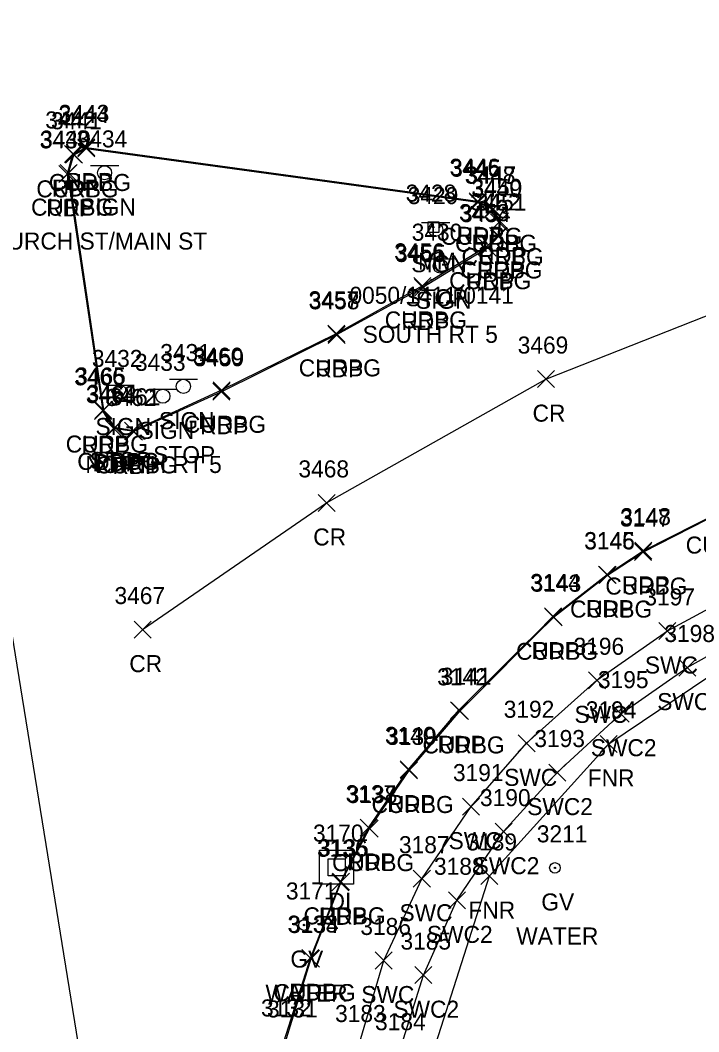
# Model space of a CAD drawing. Extents: x 1690689 to 1696275, y 438760 to 444007.
# Drawn here: x 1691116.4 to 1691196.2, y 442311.5 to 442430.3 of the extents above; entities that cross this region are included whole.
import ezdxf

# ---------------------------------------------------------------- set-up
doc = ezdxf.new("R2010")
doc.units = 0
for name, color, linetype in [('D_A', 7, 'Continuous'), ('D_I', 7, 'Continuous'), ('DS', 7, 'Continuous'), ('L_A', 7, 'Continuous'), ('L_I', 7, 'Continuous'), ('L_TIC', 7, 'Continuous'), ('LFNC', 7, 'Continuous'), ('P_A', 7, 'Continuous'), ('P_I', 7, 'Continuous'), ('P_TIC', 7, 'Continuous'), ('PET', 7, 'Continuous'), ('PRC', 7, 'Continuous'), ('R_A', 7, 'Continuous'), ('R_I', 7, 'Continuous'), ('R_TIC', 7, 'Continuous'), ('RC', 7, 'Continuous'), ('RSW', 7, 'Continuous'), ('S_A', 7, 'Continuous'), ('S_C', 7, 'Continuous'), ('S_I', 7, 'Continuous'), ('SRM', 7, 'Continuous'), ('SSGN', 7, 'Continuous'), ('U_A', 7, 'Continuous'), ('U_C', 7, 'Continuous'), ('U_I', 7, 'Continuous'), ('UWV', 7, 'Continuous')]:
    doc.layers.add(name, color=color, linetype=linetype)

msp = doc.modelspace()

# ---------------------------------------------------------------- linework, layer by layer
at = {"layer": 'DS'}
for p, q in [((1691151.61, 442332.83), (1691155.61, 442332.83)), ((1691151.61, 442328.83), (1691151.61, 442332.83)), ((1691155.61, 442332.83), (1691155.61, 442328.83)), ((1691152.61, 442329.83), (1691152.61, 442331.83)), ((1691152.61, 442331.83), (1691154.61, 442331.83)), ((1691154.61, 442331.83), (1691154.61, 442329.83)), ((1691154.61, 442329.83), (1691152.61, 442329.83)), ((1691153.62, 442330.84), (1691153.62, 442330.84)), ((1691153.62, 442330.84), (1691153.62, 442330.84)), ((1691155.61, 442328.83), (1691151.61, 442328.83))]:
    msp.add_line(p, q, dxfattribs=at)
at = {"layer": 'L_TIC'}
for points in [[(1691184.61, 442344.32), (1691186.61, 442346.32)], [(1691186.61, 442344.32), (1691184.61, 442346.32)], [(1691170.58, 442328.8), (1691172.58, 442330.8)], [(1691172.58, 442328.8), (1691170.58, 442330.8)]]:
    msp.add_lwpolyline(points, dxfattribs=at)
at = {"layer": 'LFNC'}
msp.add_lwpolyline([(1691164.13, 442250.32), (1691161.43, 442265.64), (1691160.13, 442277.98), (1691159.64, 442292.43), (1691171.58, 442329.8), (1691185.61, 442345.32), (1691203.26, 442357.19), (1691223.43, 442363.14), (1691244.19, 442366.11)], dxfattribs=at)
at = {"layer": 'P_TIC'}
for points in [[(1691121.62, 442413.63), (1691123.62, 442415.63)], [(1691123.62, 442413.63), (1691121.62, 442415.63)], [(1691123.2, 442414.4), (1691125.2, 442416.4)], [(1691125.2, 442414.4), (1691123.2, 442416.4)], [(1691120.97, 442411.29), (1691122.97, 442413.29)], [(1691122.97, 442411.29), (1691120.97, 442413.29)], [(1691120.97, 442411.29), (1691122.97, 442413.29)], [(1691122.97, 442411.29), (1691120.97, 442413.29)], [(1691169.21, 442408.07), (1691171.21, 442410.07)], [(1691171.21, 442408.07), (1691169.21, 442410.07)], [(1691171.04, 442407.16), (1691173.04, 442409.16)], [(1691173.04, 442407.16), (1691171.04, 442409.16)], [(1691171.84, 442405.7), (1691173.84, 442407.7)], [(1691173.84, 442405.7), (1691171.84, 442407.7)], [(1691171.68, 442403.98), (1691173.68, 442405.98)], [(1691173.68, 442403.98), (1691171.68, 442405.98)], [(1691170.39, 442402.62), (1691172.39, 442404.62)], [(1691172.39, 442402.62), (1691170.39, 442404.62)], [(1691162.76, 442397.94), (1691164.76, 442399.94)], [(1691164.76, 442397.94), (1691162.76, 442399.94)], [(1691152.62, 442392.38), (1691154.62, 442394.38)], [(1691154.62, 442392.38), (1691152.62, 442394.38)], [(1691177.23, 442387.18), (1691179.23, 442389.18)], [(1691179.23, 442387.18), (1691177.23, 442389.18)], [(1691139.07, 442385.69), (1691141.07, 442387.69)], [(1691141.07, 442385.69), (1691139.07, 442387.69)], [(1691125.13, 442383.45), (1691127.13, 442385.45)], [(1691127.13, 442383.45), (1691125.13, 442385.45)], [(1691125.13, 442383.45), (1691127.13, 442385.45)], [(1691127.13, 442383.45), (1691125.13, 442385.45)], [(1691126.43, 442381.36), (1691128.43, 442383.36)], [(1691128.43, 442381.36), (1691126.43, 442383.36)], [(1691128.78, 442381.02), (1691130.78, 442383.02)], [(1691130.78, 442381.02), (1691128.78, 442383.02)], [(1691151.44, 442372.63), (1691153.44, 442374.63)], [(1691153.44, 442372.63), (1691151.44, 442374.63)], [(1691188.67, 442367.02), (1691190.67, 442369.02)], [(1691190.67, 442367.02), (1691188.67, 442369.02)], [(1691184.42, 442364.21), (1691186.42, 442366.21)], [(1691186.42, 442364.21), (1691184.42, 442366.21)], [(1691178.07, 442359.29), (1691180.07, 442361.29)], [(1691180.07, 442359.29), (1691178.07, 442361.29)], [(1691129.81, 442357.75), (1691131.81, 442359.75)], [(1691131.81, 442357.75), (1691129.81, 442359.75)], [(1691167, 442348.27), (1691169, 442350.27)], [(1691169, 442348.27), (1691167, 442350.27)], [(1691161.08, 442341.32), (1691163.08, 442343.32)], [(1691163.08, 442341.32), (1691161.08, 442343.32)], [(1691156.38, 442334.47), (1691158.38, 442336.47)], [(1691158.38, 442334.47), (1691156.38, 442336.47)], [(1691153.06, 442328.06), (1691155.06, 442330.06)], [(1691155.06, 442328.06), (1691153.06, 442330.06)], [(1691149.53, 442319.15), (1691151.53, 442321.15)], [(1691151.53, 442319.15), (1691149.53, 442321.15)]]:
    msp.add_lwpolyline(points, dxfattribs=at)
at = {"layer": 'PET'}
for points in [[(1691121.97, 442412.29), (1691122.62, 442414.63), (1691124.2, 442415.4), (1691170.21, 442409.07), (1691172.04, 442408.16), (1691172.84, 442406.7), (1691172.68, 442404.98), (1691171.39, 442403.62), (1691163.76, 442398.94), (1691153.62, 442393.38), (1691140.07, 442386.69), (1691129.78, 442382.02), (1691127.43, 442382.36), (1691126.13, 442384.45)], [(1691121.97, 442412.29), (1691126.13, 442384.45)], [(1691147.42, 442310.3), (1691150.53, 442320.15), (1691154.06, 442329.06), (1691157.38, 442335.47), (1691162.08, 442342.32), (1691168, 442349.27), (1691179.07, 442360.29), (1691185.42, 442365.21), (1691189.67, 442368.02), (1691199.04, 442372.75), (1691205.16, 442375.21), (1691212.79, 442377.84), (1691220.73, 442380.07), (1691237.55, 442384.25), (1691258.48, 442389.38), (1691261.52, 442389.58), (1691265.35, 442388.29), (1691276.53, 442377.73), (1691276.93, 442377.8)]]:
    msp.add_lwpolyline(points, dxfattribs=at)
at = {"layer": 'PRC'}
for points in [[(1691277.81, 441080.96), (1691253.5, 441214.94), (1691246.19, 441267.52), (1691239.79, 441327.83), (1691235.79, 441375.29), (1691233.27, 441422.2), (1691229.73, 441505.18), (1691226.6, 441557.92), (1691222.02, 441618.83), (1691218.57, 441657.04), (1691144.02, 442182.42), (1691112.43, 442376.83), (1691097.75, 442454.48), (1691089.73, 442499.13), (1691078.44, 442565.84)], [(1691130.81, 442358.75), (1691152.44, 442373.63), (1691178.23, 442388.18), (1691209.8, 442400.63), (1691248.04, 442408.48), (1691275.24, 442412.28), (1691309.15, 442415.93), (1691347.17, 442419.98), (1691395.19, 442425.91), (1691433.65, 442431.72), (1691478.76, 442438.88), (1691513.2, 442445.49), (1691566.06, 442456.6), (1691813.76, 442512.5), (1691980.06, 442550.02), (1692039.61, 442563.23)]]:
    msp.add_lwpolyline(points, dxfattribs=at)
at = {"layer": 'R_TIC'}
for points in [[(1691121.73, 442413.53), (1691123.73, 442415.53)], [(1691123.73, 442413.53), (1691121.73, 442415.53)], [(1691123.18, 442414.28), (1691125.18, 442416.28)], [(1691125.18, 442414.28), (1691123.18, 442416.28)], [(1691121.1, 442411.38), (1691123.1, 442413.38)], [(1691123.1, 442411.38), (1691121.1, 442413.38)], [(1691121.1, 442411.38), (1691123.1, 442413.38)], [(1691123.1, 442411.38), (1691121.1, 442413.38)], [(1691169.24, 442407.96), (1691171.24, 442409.96)], [(1691171.24, 442407.96), (1691169.24, 442409.96)], [(1691170.95, 442407.14), (1691172.95, 442409.14)], [(1691172.95, 442407.14), (1691170.95, 442409.14)], [(1691171.72, 442405.58), (1691173.72, 442407.58)], [(1691173.72, 442405.58), (1691171.72, 442407.58)], [(1691171.58, 442404), (1691173.58, 442406)], [(1691173.58, 442404), (1691171.58, 442406)], [(1691170.27, 442402.74), (1691172.27, 442404.74)], [(1691172.27, 442402.74), (1691170.27, 442404.74)], [(1691162.7, 442398.13), (1691164.7, 442400.13)], [(1691164.7, 442398.13), (1691162.7, 442400.13)], [(1691152.58, 442392.5), (1691154.58, 442394.5)], [(1691154.58, 442392.5), (1691152.58, 442394.5)], [(1691139.09, 442385.87), (1691141.09, 442387.87)], [(1691141.09, 442385.87), (1691139.09, 442387.87)], [(1691125.19, 442383.55), (1691127.19, 442385.55)], [(1691127.19, 442383.55), (1691125.19, 442385.55)], [(1691125.19, 442383.55), (1691127.19, 442385.55)], [(1691127.19, 442383.55), (1691125.19, 442385.55)], [(1691126.54, 442381.51), (1691128.54, 442383.51)], [(1691128.54, 442381.51), (1691126.54, 442383.51)], [(1691128.68, 442381.1), (1691130.68, 442383.1)], [(1691130.68, 442381.1), (1691128.68, 442383.1)], [(1691188.64, 442366.86), (1691190.64, 442368.86)], [(1691190.64, 442366.86), (1691188.64, 442368.86)], [(1691184.49, 442364.16), (1691186.49, 442366.16)], [(1691186.49, 442364.16), (1691184.49, 442366.16)], [(1691178.14, 442359.2), (1691180.14, 442361.2)], [(1691180.14, 442359.2), (1691178.14, 442361.2)], [(1691191.51, 442357.59), (1691193.51, 442359.59)], [(1691193.51, 442357.59), (1691191.51, 442359.59)], [(1691193.85, 442353.29), (1691195.85, 442355.29)], [(1691195.85, 442353.29), (1691193.85, 442355.29)], [(1691183.23, 442351.79), (1691185.23, 442353.79)], [(1691185.23, 442351.79), (1691183.23, 442353.79)], [(1691167.14, 442348.2), (1691169.14, 442350.2)], [(1691169.14, 442348.2), (1691167.14, 442350.2)], [(1691186.04, 442347.87), (1691188.04, 442349.87)], [(1691188.04, 442347.87), (1691186.04, 442349.87)], [(1691174.96, 442344.39), (1691176.96, 442346.39)], [(1691176.96, 442344.39), (1691174.96, 442346.39)], [(1691161.15, 442341.2), (1691163.15, 442343.2)], [(1691163.15, 442341.2), (1691161.15, 442343.2)], [(1691178.56, 442340.95), (1691180.56, 442342.95)], [(1691180.56, 442340.95), (1691178.56, 442342.95)], [(1691168.43, 442336.95), (1691170.43, 442338.95)], [(1691170.43, 442336.95), (1691168.43, 442338.95)], [(1691156.5, 442334.37), (1691158.5, 442336.37)], [(1691158.5, 442334.37), (1691156.5, 442336.37)], [(1691172.26, 442334.01), (1691174.26, 442336.01)], [(1691174.26, 442334.01), (1691172.26, 442336.01)], [(1691153.14, 442328.12), (1691155.14, 442330.12)], [(1691155.14, 442328.12), (1691153.14, 442330.12)], [(1691162.64, 442328.48), (1691164.64, 442330.48)], [(1691164.64, 442328.48), (1691162.64, 442330.48)], [(1691166.77, 442325.94), (1691168.77, 442327.94)], [(1691168.77, 442325.94), (1691166.77, 442327.94)], [(1691149.62, 442319.1), (1691151.62, 442321.1)], [(1691151.62, 442319.1), (1691149.62, 442321.1)], [(1691158.16, 442318.87), (1691160.16, 442320.87)], [(1691160.16, 442318.87), (1691158.16, 442320.87)], [(1691162.82, 442317.15), (1691164.82, 442319.15)], [(1691164.82, 442317.15), (1691162.82, 442319.15)]]:
    msp.add_lwpolyline(points, dxfattribs=at)
at = {"layer": 'RC'}
for points in [[(1691122.1, 442412.38), (1691122.73, 442414.53), (1691124.18, 442415.28), (1691170.24, 442408.96), (1691171.95, 442408.14), (1691172.72, 442406.58), (1691172.58, 442405), (1691171.27, 442403.74), (1691163.7, 442399.13), (1691153.58, 442393.5), (1691140.09, 442386.87), (1691129.68, 442382.1), (1691127.54, 442382.51), (1691126.19, 442384.55)], [(1691122.1, 442412.38), (1691126.19, 442384.55)], [(1691147.57, 442310.18), (1691150.62, 442320.1), (1691154.14, 442329.12), (1691157.5, 442335.37), (1691162.15, 442342.2), (1691168.14, 442349.2), (1691179.14, 442360.2), (1691185.49, 442365.16), (1691189.64, 442367.86), (1691199.09, 442372.68), (1691205.19, 442375.1), (1691212.81, 442377.67), (1691220.87, 442380.02), (1691237.57, 442384.16), (1691258.28, 442388.95)]]:
    msp.add_lwpolyline(points, dxfattribs=at)
at = {"layer": 'RSW'}
for points in [[(1691173.65, 442147.45), (1691164.24, 442181.45), (1691159.6, 442182.06), (1691158.97, 442186.8), (1691163.01, 442188.55), (1691166.55, 442192.36), (1691154.22, 442268.79), (1691153.3, 442278.85), (1691153.14, 442289.14), (1691154.2, 442299.81), (1691156.14, 442309.64), (1691159.16, 442319.87), (1691163.64, 442329.48), (1691169.43, 442337.95), (1691175.96, 442345.39), (1691184.23, 442352.79), (1691192.51, 442358.59), (1691201.39, 442363.4), (1691210.8, 442367.4), (1691220.98, 442369.51), (1691275.77, 442377.07), (1691323.58, 442378.78), (1691431.09, 442393.37)], [(1691168.85, 442209.69), (1691163.66, 442242.11), (1691162.54, 442249.93), (1691158.99, 442269.5), (1691158.08, 442288.93), (1691158.91, 442298.99), (1691160.84, 442308.68), (1691163.82, 442318.15), (1691167.77, 442326.94), (1691173.26, 442335.01), (1691179.56, 442341.95), (1691187.04, 442348.87), (1691194.85, 442354.29), (1691203.45, 442359.11), (1691212.34, 442362.71), (1691221.77, 442364.59), (1691276.88, 442372.18)]]:
    msp.add_lwpolyline(points, dxfattribs=at)
at = {"layer": 'SRM'}
msp.add_lwpolyline([(1691164.38, 442406.65), (1691165.63, 442406.65), (1691165.63, 442405.4), (1691164.38, 442405.4)], close=True, dxfattribs=at)
msp.add_circle((1691165, 442406.03), 0.0833, dxfattribs=at)
at = {"layer": 'SSGN'}
for p, q in [((1691124.68, 442413.26), (1691128.01, 442413.26)), ((1691126.33, 442412.42), (1691126.33, 442412.42)), ((1691163.62, 442406.59), (1691166.95, 442406.59)), ((1691165.26, 442405.76), (1691165.26, 442405.76)), ((1691164.17, 442402.29), (1691167.5, 442402.29)), ((1691165.81, 442401.46), (1691165.81, 442401.46)), ((1691133.95, 442388.16), (1691137.28, 442388.16)), ((1691126.47, 442387.46), (1691129.8, 442387.46)), ((1691131.55, 442387), (1691134.88, 442387)), ((1691135.6, 442387.32), (1691135.6, 442387.32)), ((1691128.12, 442386.63), (1691128.12, 442386.63)), ((1691133.19, 442386.17), (1691133.19, 442386.17))]:
    msp.add_line(p, q, dxfattribs=at)
for centre in [(1691126.33, 442412.42), (1691165.26, 442405.76), (1691165.81, 442401.46), (1691135.6, 442387.32), (1691128.12, 442386.63), (1691133.19, 442386.17)]:
    msp.add_circle(centre, 0.833, dxfattribs=at)
at = {"layer": 'UWV'}
for centre, radius in [((1691179.29, 442330.75), 0.625), ((1691179.29, 442330.75), 0.0833), ((1691149.79, 442324.04), 0.625), ((1691149.79, 442324.04), 0.0833)]:
    msp.add_circle(centre, radius, dxfattribs=at)

# ---------------------------------------------------------------- texts
at = {"layer": 'D_A'}
msp.add_text('DI', height=2, dxfattribs=at).set_placement((1691152.67, 442325.84))
at = {"layer": 'D_I'}
msp.add_text('3170', height=2, dxfattribs=at).set_placement((1691150.84, 442333.84))
at = {"layer": 'L_A'}
for p in [(1691183.15, 442340.32), (1691169.12, 442324.8)]:
    msp.add_text('FNR', height=2, dxfattribs=at).set_placement(p)
at = {"layer": 'L_I'}
for s, p in [('3194', (1691182.92, 442348.32)), ('3189', (1691168.88, 442332.8))]:
    msp.add_text(s, height=2, dxfattribs=at).set_placement(p)
at = {"layer": 'P_A'}
for s, p in [('RDP', (1691121.69, 442410.4)), ('RDP', (1691120.11, 442409.63)), ('RDP', (1691119.45, 442407.29)), ('RDP', (1691119.45, 442407.29)), ('RDP', (1691167.7, 442404.07)), ('RDP', (1691169.52, 442403.16)), ('RDP', (1691170.33, 442401.7)), ('RDP', (1691170.16, 442399.98)), ('RDP', (1691168.88, 442398.62)), ('RDP', (1691161.24, 442393.94)), ('RDP', (1691151.11, 442388.38)), ('CR', (1691176.66, 442383.18)), ('RDP', (1691137.56, 442381.69)), ('RDP', (1691123.61, 442379.45)), ('RDP', (1691123.61, 442379.45)), ('RDP', (1691124.92, 442377.36)), ('RDP', (1691127.26, 442377.02)), ('CR', (1691150.87, 442368.63)), ('RDP', (1691187.16, 442363.02)), ('RDP', (1691182.91, 442360.21)), ('RDP', (1691176.55, 442355.29)), ('CR', (1691129.24, 442353.75)), ('RDP', (1691165.48, 442344.27)), ('RDP', (1691159.57, 442337.32)), ('RDP', (1691154.87, 442330.47)), ('RDP', (1691151.54, 442324.06)), ('RDP', (1691148.02, 442315.15))]:
    msp.add_text(s, height=2, dxfattribs=at).set_placement(p)
at = {"layer": 'P_I'}
for s, p in [('3443', (1691120.94, 442418.4)), ('3442', (1691119.36, 442417.63)), ('3439', (1691118.7, 442415.29)), ('3439', (1691118.7, 442415.29)), ('3446', (1691166.9, 442412.07)), ('3447', (1691168.78, 442411.16)), ('3450', (1691169.49, 442409.7)), ('3451', (1691169.98, 442407.98)), ('3454', (1691168.13, 442406.62)), ('3455', (1691160.5, 442401.94)), ('3458', (1691150.36, 442396.38)), ('3469', (1691174.91, 442391.18)), ('3459', (1691136.8, 442389.69)), ('3466', (1691122.76, 442387.45)), ('3466', (1691122.76, 442387.45)), ('3463', (1691124.13, 442385.36)), ('3462', (1691126.47, 442385.02)), ('3468', (1691149.13, 442376.63)), ('3148', (1691186.98, 442371.02)), ('3145', (1691182.73, 442368.21)), ('3144', (1691176.37, 442363.29)), ('3467', (1691127.5, 442361.75)), ('3141', (1691165.87, 442352.27)), ('3140', (1691159.3, 442345.32)), ('3137', (1691154.68, 442338.47)), ('3136', (1691151.31, 442332.06)), ('3133', (1691147.84, 442323.15)), ('3132', (1691144.73, 442313.3))]:
    msp.add_text(s, height=2, dxfattribs=at).set_placement(p)
at = {"layer": 'R_A'}
for s, p in [('CURBG', (1691119.77, 442410.28)), ('CURBG', (1691118.31, 442409.53)), ('CURBG', (1691117.69, 442407.38)), ('CURBG', (1691117.69, 442407.38)), ('CURBG', (1691165.82, 442403.96)), ('CURBG', (1691167.54, 442403.14)), ('CURBG', (1691168.31, 442401.58)), ('CURBG', (1691168.17, 442400)), ('CURBG', (1691166.85, 442398.74)), ('CURBG', (1691159.28, 442394.13)), ('CURBG', (1691149.17, 442388.5)), ('CURBG', (1691135.67, 442381.87)), ('CURBG', (1691121.77, 442379.55)), ('CURBG', (1691121.77, 442379.55)), ('CURBG', (1691123.12, 442377.51)), ('CURBG', (1691125.26, 442377.1)), ('CURBG', (1691194.67, 442367.68)), ('CURBG', (1691185.22, 442362.86)), ('CURBG', (1691181.07, 442360.16)), ('CURBG', (1691174.72, 442355.2)), ('SWC', (1691189.87, 442353.59)), ('SWC2', (1691191.32, 442349.29)), ('SWC', (1691181.59, 442347.79)), ('CURBG', (1691163.72, 442344.2)), ('SWC2', (1691183.51, 442343.87)), ('SWC', (1691173.32, 442340.39)), ('CURBG', (1691157.73, 442337.2)), ('SWC2', (1691176.03, 442336.95)), ('SWC', (1691166.79, 442332.95)), ('CURBG', (1691153.08, 442330.37)), ('SWC2', (1691169.73, 442330.01)), ('SWC', (1691161.01, 442324.48)), ('CURBG', (1691149.72, 442324.12)), ('SWC2', (1691164.24, 442321.94)), ('CURBG', (1691146.2, 442315.1)), ('SWC', (1691156.52, 442314.87)), ('SWC2', (1691160.3, 442313.15))]:
    msp.add_text(s, height=2, dxfattribs=at).set_placement(p)
at = {"layer": 'R_I'}
for s, p in [('3444', (1691120.92, 442418.28)), ('3441', (1691120.04, 442417.53)), ('3440', (1691118.76, 442415.38)), ('3440', (1691118.76, 442415.38)), ('3445', (1691166.98, 442411.96)), ('3448', (1691168.69, 442411.14)), ('3449', (1691169.46, 442409.58)), ('3452', (1691169.32, 442408)), ('3453', (1691168.01, 442406.74)), ('3456', (1691160.39, 442402.13)), ('3457', (1691150.32, 442396.5)), ('3460', (1691136.7, 442389.87)), ('3465', (1691122.88, 442387.55)), ('3465', (1691122.88, 442387.55)), ('3464', (1691124.23, 442385.51)), ('3461', (1691126.94, 442385.1)), ('3147', (1691186.94, 442370.86)), ('3146', (1691182.74, 442368.16)), ('3143', (1691176.44, 442363.2)), ('3197', (1691189.81, 442361.59)), ('3198', (1691192.16, 442357.29)), ('3196', (1691181.48, 442355.79)), ('3142', (1691165.44, 442352.2)), ('3195', (1691184.35, 442351.87)), ('3192', (1691173.27, 442348.39)), ('3139', (1691159.45, 442345.2)), ('3193', (1691176.87, 442344.95)), ('3191', (1691167.3, 442340.95)), ('3138', (1691154.81, 442338.37)), ('3190', (1691170.48, 442338.01)), ('3135', (1691151.45, 442332.12)), ('3187', (1691160.95, 442332.48)), ('3188', (1691165.07, 442329.94)), ('3134', (1691147.93, 442323.1)), ('3186', (1691156.41, 442322.87)), ('3185', (1691161.13, 442321.15)), ('3131', (1691145.44, 442313.18)), ('3183', (1691153.44, 442312.64)), ('3184', (1691158.14, 442311.68))]:
    msp.add_text(s, height=2, dxfattribs=at).set_placement(p)
at = {"layer": 'S_A'}
for s, p in [('SIGN', (1691123.46, 442407.4)), ('SIGN', (1691162.4, 442400.74)), ('MM', (1691163.19, 442401.03)), ('SIGN', (1691162.95, 442396.44)), ('SIGN', (1691125.26, 442381.61)), ('SIGN', (1691132.73, 442382.3)), ('SIGN', (1691130.33, 442381.15))]:
    msp.add_text(s, height=2, dxfattribs=at).set_placement(p)
at = {"layer": 'S_C'}
for s, p in [('CHURCH ST/MAIN ST', (1691111.06, 442403.4)), ('0050/1411/0141', (1691155.13, 442397.03)), ('STOP', (1691161.73, 442396.74)), ('SOUTH RT 5', (1691156.68, 442392.44)), ('STOP', (1691132.06, 442378.3)), ('NORTH RT 5', (1691124.07, 442377.15)), ('STOP', (1691124.58, 442377.61))]:
    msp.add_text(s, height=2, dxfattribs=at).set_placement(p)
at = {"layer": 'S_I'}
for s, p in [('3434', (1691123.05, 442415.4)), ('3428', (1691161.74, 442409.03)), ('3429', (1691161.98, 442408.74)), ('3430', (1691162.45, 442404.44)), ('3432', (1691124.84, 442389.61)), ('3431', (1691132.88, 442390.3)), ('3433', (1691129.91, 442389.15))]:
    msp.add_text(s, height=2, dxfattribs=at).set_placement(p)
at = {"layer": 'U_A'}
for p in [(1691177.69, 442325.75), (1691148.19, 442319.04)]:
    msp.add_text('GV', height=2, dxfattribs=at).set_placement(p)
at = {"layer": 'U_C'}
for p in [(1691174.74, 442321.75), (1691145.25, 442315.04)]:
    msp.add_text('WATER', height=2, dxfattribs=at).set_placement(p)
at = {"layer": 'U_I'}
for s, p in [('3211', (1691177.16, 442333.75)), ('3171', (1691147.66, 442327.04))]:
    msp.add_text(s, height=2, dxfattribs=at).set_placement(p)

doc.saveas('drawing.dxf')
